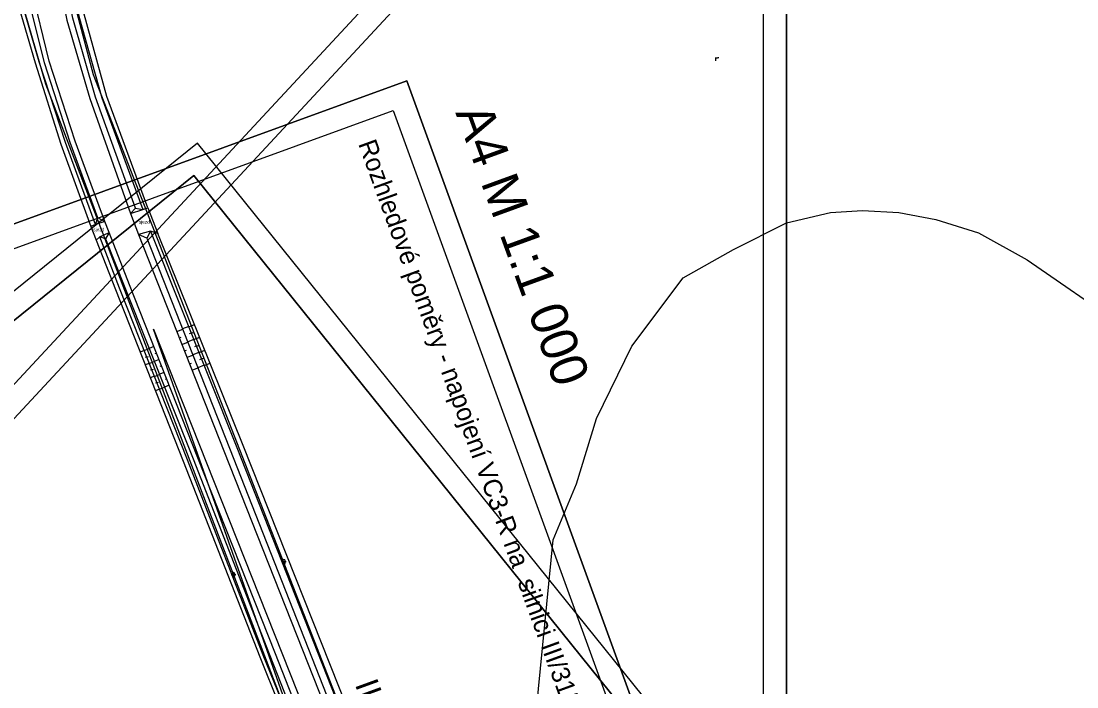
# Model space of a CAD drawing. Extents: x -555887 to -552101, y -1100251 to -1096546.
# Drawn here: x -554805 to -554576.9, y -1098193.1 to -1098049.3 of the extents above; entities that cross this region are included whole.
import ezdxf

# ---------------------------------------------------------------- set-up
doc = ezdxf.new("R2010")
doc.units = 0
for name, color, linetype in [('PARCELY_silnice', 7, 'Continuous'), ('ram_VC1', 7, 'Continuous'), ('ram_VC3-R', 7, 'Continuous'), ('ram_VC4', 7, 'Continuous'), ('ROZHLED_ram_legenda_2', 7, 'Continuous'), ('ROZHLED_trojuhelniky_2', 7, 'Continuous'), ('vrstevnice', 7, 'Continuous'), ('ZSST', 7, 'Continuous')]:
    doc.layers.add(name, color=color, linetype=linetype)

msp = doc.modelspace()

# ---------------------------------------------------------------- linework, layer by layer
at = {"layer": 'PARCELY_silnice'}
msp.add_lwpolyline([(-554723.86, -1098228.82), (-554789.41, -1098060.89), (-554795.49, -1098037.68), (-554798.79, -1098015.89), (-554799.97, -1097996.99), (-554801.13, -1097979.06), (-554810.02, -1097836.83), (-554816.13, -1097801.76), (-554879.07, -1097590.15), (-554882.77, -1097577.71), (-554885.93, -1097567.08), (-554889.29, -1097569.68), (-554893.97, -1097573.72), (-554896.43, -1097575.85), (-554890.98, -1097593.9), (-554886.96, -1097607.2), (-554827.57, -1097803.83), (-554820.38, -1097838.69), (-554809.61, -1098016.32), (-554806.44, -1098039.59), (-554799.78, -1098062.8), (-554737.92, -1098224.21)], dxfattribs=at)
at = {"layer": 'ram_VC1'}
for points in [[(-554540.88, -1097849.11), (-554911.62, -1097504.63), (-555880.62, -1098547.51), (-555509.88, -1098891.98)], [(-554547.95, -1097849.37), (-554911.36, -1097511.7), (-555873.55, -1098547.25), (-555510.14, -1098884.91)]]:
    msp.add_lwpolyline(points, close=True, dxfattribs=at)
for points in [[(-554540.88, -1097849.11), (-554911.62, -1097504.63), (-555880.62, -1098547.51), (-555509.88, -1098891.98), (-554540.88, -1097849.11)], [(-555510.14, -1098884.91), (-555873.55, -1098547.25), (-554911.36, -1097511.7), (-554547.95, -1097849.37), (-555510.14, -1098884.91)]]:
    msp.add_lwpolyline(points, dxfattribs=at)
at = {"layer": 'ram_VC3-R'}
for points in [[(-554580.57, -1098306.86), (-554766.92, -1098075.6), (-555584.52, -1098734.41), (-555398.17, -1098965.67), (-554580.57, -1098306.86)], [(-555397.41, -1098958.64), (-555577.49, -1098735.16), (-554767.68, -1098082.63), (-554587.6, -1098306.1), (-555397.41, -1098958.64)]]:
    msp.add_lwpolyline(points, dxfattribs=at)
for points in [[(-554580.57, -1098306.86), (-554766.92, -1098075.6), (-555584.52, -1098734.41), (-555398.17, -1098965.67)], [(-554587.6, -1098306.1), (-554767.68, -1098082.63), (-555577.49, -1098735.16), (-555397.41, -1098958.64)]]:
    msp.add_lwpolyline(points, close=True, dxfattribs=at)
at = {"layer": 'ram_VC4'}
for points in [[(-554287.63, -1097875.47), (-554644.63, -1097875.47), (-554644.63, -1098505.47), (-554287.63, -1098505.47)], [(-554292.63, -1097880.47), (-554639.63, -1097880.47), (-554639.63, -1098500.47), (-554292.63, -1098500.47)]]:
    msp.add_lwpolyline(points, close=True, dxfattribs=at)
for points in [[(-554287.63, -1097875.47), (-554644.63, -1097875.47), (-554644.63, -1098505.47), (-554287.63, -1098505.47), (-554287.63, -1097875.47)], [(-554292.63, -1098500.47), (-554639.63, -1098500.47), (-554639.63, -1097880.47), (-554292.63, -1097880.47), (-554292.63, -1098500.47)]]:
    msp.add_lwpolyline(points, dxfattribs=at)
at = {"layer": 'ROZHLED_ram_legenda_2'}
msp.add_lwpolyline([(-554620.13, -1098341.26), (-554817.47, -1098413.06), (-554919.02, -1098133.96), (-554721.68, -1098062.16)], close=True, dxfattribs=at)
msp.add_lwpolyline([(-554620.13, -1098341.26), (-554817.47, -1098413.06), (-554919.02, -1098133.96), (-554721.68, -1098062.16)], close=True, dxfattribs=at)
for points in [[(-554721.68, -1098062.16), (-554919.02, -1098133.96), (-554817.47, -1098413.06), (-554620.13, -1098341.26), (-554721.68, -1098062.16)], [(-554814.48, -1098406.65), (-554912.61, -1098136.95), (-554724.66, -1098068.57), (-554626.53, -1098338.27), (-554814.48, -1098406.65)], [(-554814.48, -1098406.65), (-554912.61, -1098136.95), (-554724.66, -1098068.57), (-554626.53, -1098338.27), (-554814.48, -1098406.65)]]:
    msp.add_lwpolyline(points, dxfattribs=at)
at = {"layer": 'ROZHLED_trojuhelniky_2'}
for p, q in [((-554776.41, -1098115.83), (-554732.27, -1098226.96)), ((-554736.16, -1098229.62), (-554776.41, -1098115.83))]:
    msp.add_line(p, q, dxfattribs=at)
at = {"layer": 'vrstevnice'}
msp.add_lwpolyline([(-554694.6, -1098207.42), (-554690.01, -1098161.35), (-554685.01, -1098149.2), (-554680.66, -1098135.09), (-554673.05, -1098119.46), (-554661.97, -1098104.7), (-554651.1, -1098098.62), (-554639.62, -1098092.86), (-554630.1, -1098090.61), (-554623.19, -1098090.19), (-554615.36, -1098090.61), (-554607.32, -1098092.09), (-554598.14, -1098094.98), (-554587.63, -1098100.82), (-554566.95, -1098115.08), (-554534.47, -1098141.9), (-554513.87, -1098156.84), (-554501.27, -1098162.95), (-554483.85, -1098171.3), (-554466.54, -1098176.35), (-554445.22, -1098180.82), (-554429.45, -1098181.06)], dxfattribs=at)
at = {"layer": 'ZSST'}
for p, q in [((-554788.5, -1098091.67), (-554786.95, -1098092.56)), ((-554771.39, -1098116.31), (-554770.11, -1098115.8)), ((-554768.82, -1098115.25), (-554770.12, -1098115.77)), ((-554768.81, -1098115.29), (-554767.57, -1098114.79)), ((-554768.26, -1098116.65), (-554768.7, -1098116.82)), ((-554768.25, -1098116.68), (-554767.84, -1098116.51)), ((-554770.83, -1098117.7), (-554770.41, -1098117.53)), ((-554770.28, -1098119.1), (-554769.01, -1098118.6)), ((-554767.71, -1098118.04), (-554769.03, -1098118.57)), ((-554767.69, -1098118.07), (-554766.44, -1098117.57)), ((-554778.45, -1098120.4), (-554779.32, -1098120.74)), ((-554778.44, -1098120.43), (-554777.37, -1098120.01)), ((-554776.32, -1098119.57), (-554777.38, -1098119.99)), ((-554775.77, -1098120.97), (-554776.12, -1098121.1)), ((-554769.73, -1098120.49), (-554769.31, -1098120.33)), ((-554769.18, -1098121.89), (-554767.92, -1098121.39)), ((-554766.59, -1098120.82), (-554767.93, -1098121.36)), ((-554767.15, -1098119.43), (-554767.59, -1098119.61)), ((-554767.14, -1098119.47), (-554766.72, -1098119.3)), ((-554766.58, -1098120.86), (-554765.32, -1098120.36)), ((-554777.35, -1098123.19), (-554778.22, -1098123.53)), ((-554777.9, -1098121.79), (-554778.19, -1098121.91)), ((-554777.88, -1098121.83), (-554777.53, -1098121.69)), ((-554777.33, -1098123.22), (-554776.26, -1098122.8)), ((-554775.22, -1098122.36), (-554776.27, -1098122.77)), ((-554768.63, -1098123.28), (-554768.21, -1098123.12)), ((-554765.48, -1098123.61), (-554766.83, -1098124.15)), ((-554766.04, -1098122.22), (-554766.48, -1098122.4)), ((-554766.02, -1098122.25), (-554765.6, -1098122.08)), ((-554765.46, -1098123.64), (-554764.2, -1098123.14)), ((-554776.24, -1098125.98), (-554777.12, -1098126.32)), ((-554776.79, -1098124.58), (-554777.08, -1098124.7)), ((-554776.78, -1098124.62), (-554776.42, -1098124.48)), ((-554776.23, -1098126.01), (-554775.14, -1098125.58)), ((-554774.12, -1098125.15), (-554775.15, -1098125.56)), ((-554774.67, -1098123.76), (-554775.02, -1098123.89)), ((-554768.08, -1098124.68), (-554766.82, -1098124.18)), ((-554775.69, -1098127.37), (-554775.98, -1098127.49)), ((-554775.67, -1098127.41), (-554775.31, -1098127.26)), ((-554773.02, -1098127.94), (-554774.04, -1098128.35)), ((-554773.57, -1098126.55), (-554773.91, -1098126.68)), ((-554775.14, -1098128.77), (-554776.01, -1098129.11)), ((-554775.12, -1098128.8), (-554774.03, -1098128.37)), ((-554747.75, -1098166.07), (-554748.75, -1098166.07)), ((-554748.5, -1098166.32), (-554748.5, -1098165.82)), ((-554748, -1098166.32), (-554748, -1098165.82)), ((-554758.63, -1098168.88), (-554759.63, -1098168.88)), ((-554759.38, -1098169.13), (-554759.38, -1098168.63)), ((-554758.88, -1098169.13), (-554758.88, -1098168.63))]:
    msp.add_line(p, q, dxfattribs=at)
for points in [[(-554378.27, -1097932.19), (-554449.89, -1097941.05), (-554490.07, -1097945.89), (-554541.16, -1097953.02), (-554579.53, -1097958.38), (-554633.43, -1097966.19), (-554669.21, -1097971.27), (-554701.17, -1097975.8), (-554741.51, -1097981.4), (-554758.22, -1097983.93), (-554789.4, -1097989.25), (-554798.91, -1097991.06), (-554801.45, -1097993.02), (-554802.6, -1097995.56), (-554801.5, -1098009.78), (-554799.51, -1098027.14), (-554795.12, -1098049.06), (-554790.18, -1098065.96), (-554781.38, -1098090.83), (-554779.66, -1098095.37), (-554761.2, -1098142.08), (-554736.99, -1098203.29)], [(-554777.63, -1098089.57), (-554786.5, -1098065.57), (-554791.43, -1098047.75), (-554795.39, -1098027.51), (-554797.81, -1098008.91), (-554797.55, -1097998.95), (-554796.07, -1097994.33), (-554788.46, -1097991.18), (-554758.19, -1097986.43), (-554741.15, -1097984.46), (-554700.68, -1097978.66), (-554670.04, -1097974.09), (-554633.76, -1097969), (-554582.2, -1097962.52), (-554542.18, -1097957.18), (-554489.66, -1097950.04)], [(-554780.34, -1098089.69), (-554788.96, -1098065.69), (-554793.85, -1098048.65), (-554798.08, -1098027.31), (-554800.02, -1098009.61), (-554801.34, -1097995.78), (-554801.45, -1097993.02)], [(-554812.85, -1097998.28), (-554811.95, -1098011), (-554809.72, -1098029.18), (-554808.37, -1098036.91), (-554806.29, -1098043.45), (-554801.98, -1098058.28), (-554796.45, -1098075.85), (-554789.96, -1098093.65)], [(-554788.96, -1098093.22), (-554795.45, -1098075.49), (-554801.12, -1098058.05), (-554805.42, -1098043.13), (-554807.97, -1098029.12), (-554810.08, -1098011.13), (-554811.13, -1097998.28)], [(-554809.55, -1097999.2), (-554808.52, -1098011.7), (-554806.56, -1098029.29), (-554803.94, -1098042.68), (-554800.07, -1098058.23), (-554794.52, -1098075.44), (-554788.5, -1098091.67), (-554788.96, -1098093.22)], [(-554798.97, -1098009.32), (-554796.76, -1098027.47), (-554792.54, -1098048.16), (-554787.58, -1098065.82), (-554778.76, -1098089.92)], [(-554735.2, -1098223.73), (-554750.09, -1098185.95), (-554766.83, -1098143.59), (-554781.61, -1098106.2), (-554786, -1098094.94), (-554786.95, -1098092.56), (-554793.37, -1098075.16), (-554798.99, -1098057.93), (-554802.81, -1098042.11), (-554805.11, -1098029.31)], [(-554654.9, -1098057.86), (-554654.9, -1098057.13)], [(-554654.9, -1098057.37), (-554654.8, -1098057.27), (-554654.7, -1098057.21), (-554654.54, -1098057.16), (-554654.39, -1098057.14), (-554654.23, -1098057.13)], [(-554781.38, -1098090.83), (-554778.76, -1098089.92), (-554777.63, -1098089.57), (-554775.48, -1098095.17), (-554777.06, -1098094.66), (-554779.66, -1098095.37)], [(-554781.38, -1098090.83), (-554780.34, -1098089.69), (-554778.76, -1098089.92)], [(-554786.95, -1098092.56), (-554788.96, -1098093.22), (-554789.96, -1098093.65), (-554788.81, -1098096.59), (-554788.04, -1098095.89), (-554786, -1098094.94)], [(-554786, -1098094.94), (-554786.79, -1098096.29), (-554788.04, -1098095.89)], [(-554736.37, -1098226.37), (-554752.72, -1098186.22), (-554769.1, -1098144), (-554783.78, -1098106.95), (-554788.04, -1098095.89)], [(-554786.79, -1098096.29), (-554782.65, -1098106.8), (-554767.87, -1098143.79), (-554751.44, -1098185.96), (-554736.72, -1098223.34), (-554735.2, -1098223.73)], [(-554777.06, -1098094.66), (-554777.83, -1098096.16), (-554779.66, -1098095.37)], [(-554777.83, -1098096.16), (-554760.01, -1098141.51), (-554735.79, -1098203.05), (-554724.07, -1098231.63), (-554717.05, -1098251.55), (-554711.12, -1098268.54), (-554702.66, -1098297.07), (-554688.13, -1098349.45), (-554678.03, -1098386.95), (-554667.31, -1098425.58), (-554665.87, -1098427.02)], [(-554777.06, -1098094.66), (-554758.38, -1098141.35), (-554734.11, -1098202.96), (-554722.58, -1098231.5), (-554716.1, -1098249.51)], [(-554664.42, -1098426.37), (-554675.26, -1098385.42), (-554685.3, -1098349.05), (-554700.53, -1098297.02), (-554708.23, -1098268.73), (-554714.81, -1098247.44), (-554721.01, -1098230.97), (-554732.6, -1098202.44), (-554757.03, -1098140.91), (-554775.48, -1098095.17)], [(-554788.81, -1098096.59), (-554784.67, -1098107.23), (-554770, -1098144.31), (-554753.44, -1098186.56), (-554737.02, -1098227.49)]]:
    msp.add_lwpolyline(points, dxfattribs=at)
for centre, start, end in [((-554748.25, -1098165.82), 0, 180), ((-554748.25, -1098166.32), 180, 0), ((-554759.13, -1098168.63), 0, 180), ((-554759.13, -1098169.13), 180, 0)]:
    msp.add_arc(centre, 0.25, start, end, dxfattribs=at)

# ---------------------------------------------------------------- texts
at = {"layer": 'ROZHLED_ram_legenda_2'}
for s, height, rotation, p in [('A4 M 1:1 000', 8, 289.9937, (-554711.23, -1098068.98)), ('Rozhledové poměry - napojení VC3-R na  silnici III/31548', 4, 289.9937, (-554732.23, -1098075.74)), ('III/31548', 5, 289.9936, (-554732.93, -1098192.53))]:
    msp.add_text(s, height=height, rotation=rotation, dxfattribs=at).set_placement(p)
at = {"layer": 'ZSST'}
for p in [(-554789.45, -1098094.64), (-554779.62, -1098093.01)]:
    msp.add_text('sjezd', height=0.75, dxfattribs=at).set_placement(p)

doc.saveas('drawing.dxf')
